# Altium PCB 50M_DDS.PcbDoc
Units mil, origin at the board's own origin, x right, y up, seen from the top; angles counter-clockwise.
Board outline 3260 x 1620 mil, 2 copper layers (Top Layer, Bottom Layer); 21 components, 21 nets, 79 pads, 0 vias.
Unrouted connection lines stored in the file: 55.
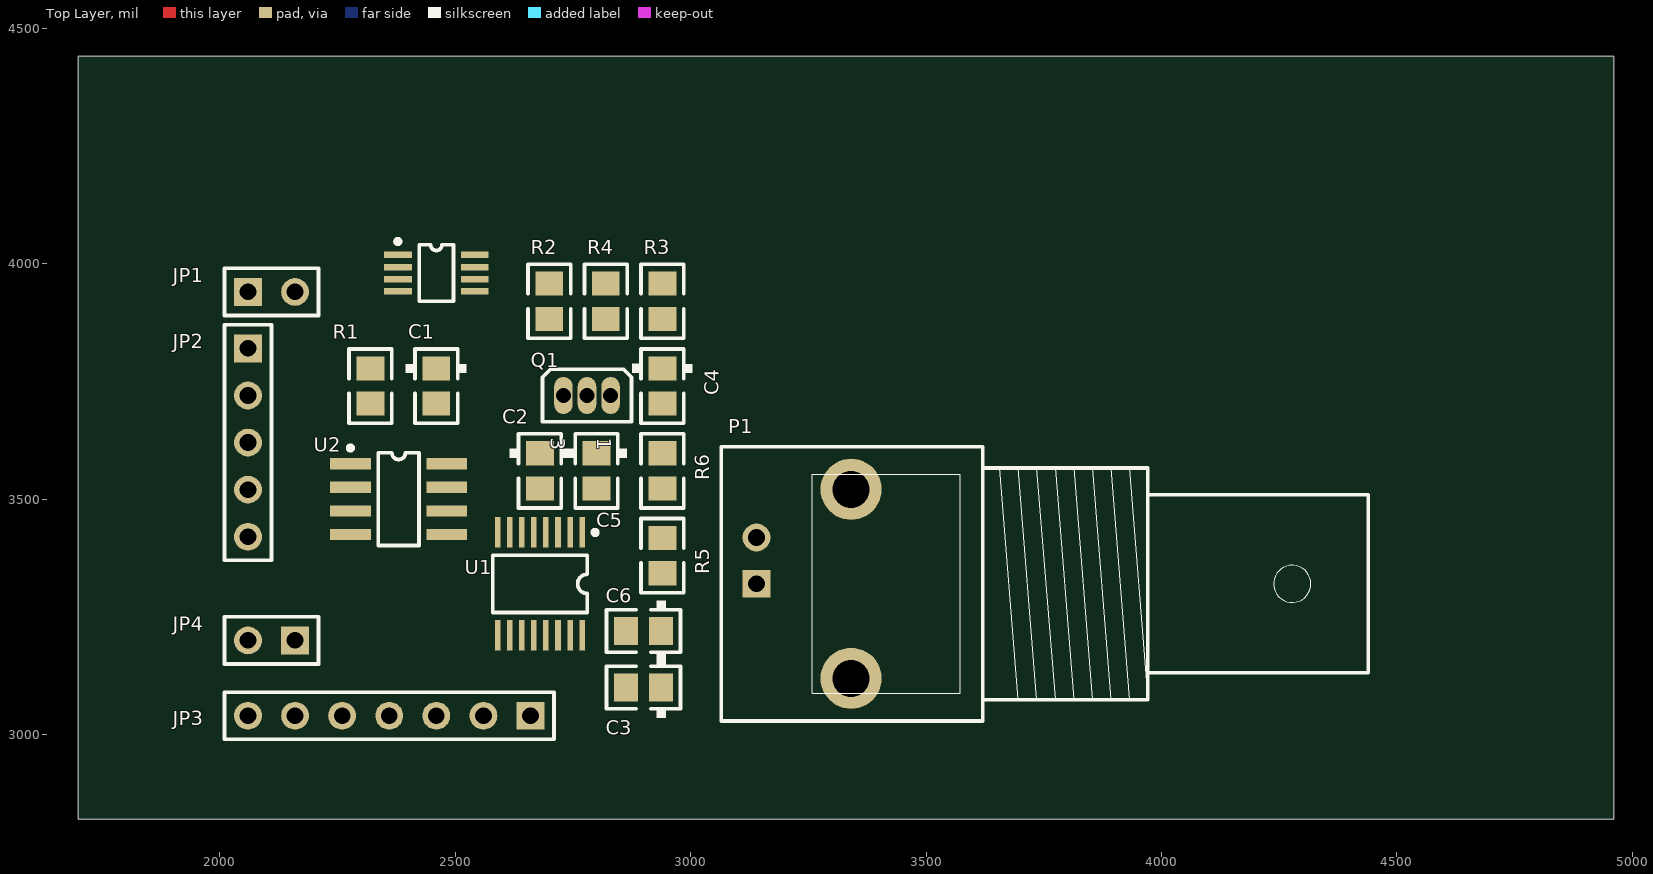
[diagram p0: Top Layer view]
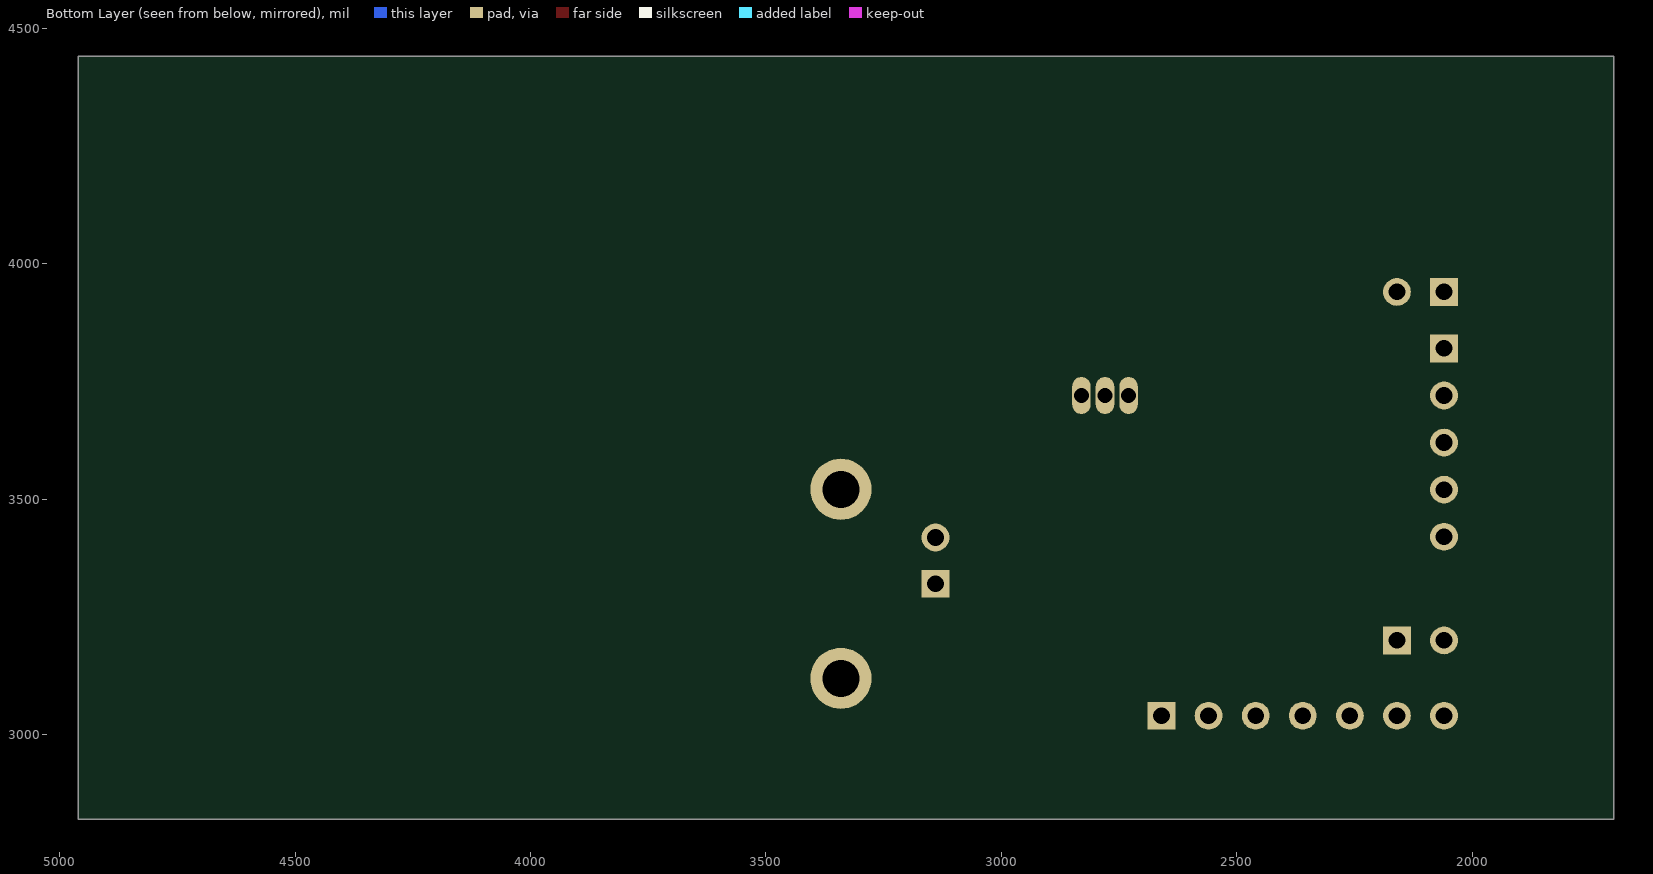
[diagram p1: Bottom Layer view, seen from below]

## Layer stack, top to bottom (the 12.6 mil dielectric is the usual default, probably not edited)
Top Layer: signal copper 1.4
Dielectric: dielectric 12.6, FR-4, Dk 4.8
Bottom Layer: signal copper 1.4

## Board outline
1700,4380 1700,2820 4960,2820 4960,4440 1700,4440

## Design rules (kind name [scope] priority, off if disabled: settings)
Clearance [All] p1: gap=10
ComponentClearance [All] p1: gap=10 collisioncheckmode=0
PolygonConnect [All] p1: connectstyle=Relief reliefconductorwidth=10 reliefentries=4 polygonreliefangle="90 Angle"
RoutingLayers [All] p1: top layer=Horizontal bottom layer=Vertical
RoutingVias [All] p1: holewidth=28 width=50 viastyle="Through Hole" minholewidth=28 minwidth=50 maxholewidth=28 maxwidth=50
SolderMaskExpansion [All] p1: expansion=4
TestPointUsage [All] p1: valid=0 allowmultiple=FALSE
Testpoint [All] p1: side=15 testpointundercomponent=TRUE minsize=40 maxsize=100 preferedsize=60 minholesize=0 maxholesize=40 preferedholesize=32 testpointgrid=1 style=1023 order=-539222988
Width [All] p1: maxlimit=10 minlimit=10 preferedwidth=10
16 further rules are at their usual default settings.

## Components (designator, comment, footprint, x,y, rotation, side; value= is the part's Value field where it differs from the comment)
C1 "100pF" CC2012-0805 2460,3740 r270 top
C2 "100pF" CC2012-0805 2680,3560 r270 top
C3 "100pF" CC2012-0805 2900,3100 r180 top
C4 "510pF" CC2012-0805 2940,3740 r270 top
C5 "100pF" CC2012-0805 2800,3560 r270 top
C6 "100pF" CC2012-0805 2900,3220 r180 top
JP1 "Header 2" HDR1X2 2060,3940 r0 top locked
JP2 "Header 5" HDR1X5 2060,3820 r270 top locked
JP3 "Header 7" HDR1X7 2660,3040 r180 top locked
JP4 "Header 2" HDR1X2 2160,3200 r180 top locked
P1 "BNC" "BNC_RA CON" 3140,3320 r180 top
Q1 "MOSFET-N" BCY-W3/H.8 2780,3720 r270 top
R1 "4.7K" R2012-0805 2320,3740 r270 top
R2 "4.7K" R2012-0805 2700,3920 r90 top
R3 "50" R2012-0805 2940,3920 r90 top
R4 "1.5K" R2012-0805 2820,3920 r270 top
R5 "300" R2012-0805 2940,3380 r270 top
R6 "4.7K" R2012-0805 2940,3560 r270 top
U1 "AD9835" TSSO5X6-G16 2680,3320 r180 top
U2 "TLC5615" SO-G8 2380,3500 r270 top
? "ADG821" TSSO3X5-G8/X.35 2460,3980 r270 top

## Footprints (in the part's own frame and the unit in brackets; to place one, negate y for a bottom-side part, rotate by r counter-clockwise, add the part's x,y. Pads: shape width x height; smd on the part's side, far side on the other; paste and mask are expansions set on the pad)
BCY-W3/H.8 [mm]
  oval 2x1 hole 0.8: 1(0,1.27) 2(0,0) 3(0,-1.27)
  silkscreen extent -1.41,-2.41 1.41,2.41
"BNC_RA CON" [mm]
  rect 1.5x1.5 hole 0.9: 1(0,0)
  round 3.3 hole 2: 2(-5.1,5.1) 2(-5.1,-5.1)
  round 1.5 hole 0.9: 2(0,-2.5)
  silkscreen extent -33,-7.4 1.9,7.4
CC2012-0805 [mm]
  rect 1.3x1.5 smd: 1(-0.95,0) 2(0.95,0)
  silkscreen extent -2,-1.65 2,1.64
HDR1X2 [mm]
  rect 1.5x1.5 hole 0.9: 1(0,0)
  round 1.5 hole 0.9: 2(2.54,0)
  silkscreen extent -1.27,-1.27 3.81,1.27
HDR1X5 [mm]
  rect 1.5x1.5 hole 0.9: 1(0,0)
  round 1.5 hole 0.9: 2(2.54,0) 3(5.08,0) 4(7.62,0) 5(10.16,0)
  silkscreen extent -1.27,-1.27 11.43,1.27
HDR1X7 [mm]
  rect 1.5x1.5 hole 0.9: 1(0,0)
  round 1.5 hole 0.9: 2(2.54,0) 3(5.08,0) 4(7.62,0) 5(10.16,0) 6(12.7,0) 7(15.24,0)
  silkscreen extent -1.27,-1.27 16.51,1.27
R2012-0805 [mm]
  rect 1.3x1.5 smd: 1(-0.95,0) 2(0.95,0)
  silkscreen extent -2,-1.15 2,1.15
SO-G8 [mm]
  rect 0.6x2.2 smd: 1(-1.905,-2.6) 2(-0.635,-2.6) 3(0.635,-2.6) 4(1.905,-2.6) 5(1.905,2.6) 6(0.635,2.6) 7(-0.635,2.6) 8(-1.905,2.6)
  silkscreen extent -2.88,-2.72 2.5,1.1
TSSO3X5-G8/X.35 [mm]
  rect 0.35x1.5 smd: 1(-0.975,-2.075) 2(-0.325,-2.075) 3(0.325,-2.075) 4(0.975,-2.075) 5(0.975,2.075) 6(0.325,2.075) 7(-0.325,2.075) 8(-0.975,2.075)
  silkscreen extent -1.82,-2.2 1.52,0.92
TSSO5X6-G16 [mm]
  rect 0.3x1.65 smd: 1(-2.275,-2.775) 2(-1.625,-2.775) 3(-0.975,-2.775) 4(-0.325,-2.775) 5(0.325,-2.775) 6(0.975,-2.775) 7(1.625,-2.775) 8(2.275,-2.775) 9(2.275,2.775) 10(1.625,2.775) 11(0.975,2.775) 12(0.325,2.775) 13(-0.325,2.775) 14(-0.975,2.775) 15(-1.625,2.775) 16(-2.275,2.775)
  silkscreen extent -3.1,-2.9 2.55,1.55

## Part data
C1 C2 C3 C4 C5 C6: library part Cap, "Capacitor"
JP1 JP4: "Header, 2-Pin"
JP2: "Header, 5-Pin"
JP3: "Header, 7-Pin"
P1: "BNC Elbow Connector"
Q1: "N-Channel MOSFET"
R1 R2 R3 R4 R5 R6: library part Res1, "Resistor"
U1: "50 MHz CMOS / Complete DDS"
U2: "10bit DA Convertor"

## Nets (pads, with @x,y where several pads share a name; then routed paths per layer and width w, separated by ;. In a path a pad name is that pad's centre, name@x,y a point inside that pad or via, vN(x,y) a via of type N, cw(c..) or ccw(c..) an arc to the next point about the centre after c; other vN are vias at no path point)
CLK: JP2.3 U2.2
D: ?.2 ?.6 Q1.2 R3.2
DIN: JP2.2 U2.1
FSEL: JP3.4 U1.10
FSYNC: JP3.5 U1.9
GND: ?.4 C1.1 C2.1 C3.1 C5.1 JP1.1 JP2.1 JP4.1 P1.1 R1.2 R3.1 R4.1 R5.1 R6.1 U1.5 U1.13 U2.3 U2.5
IN1: ?.7 JP2.5 R2.1
MCLK: JP3.1 U1.6
Net_3: ?.3 R1.1
NetC4_1: C4.1 Q1.3 R4.2
NetC5_2: C5.2 U1.2 U1.3
NetC6_2: C6.2 U1.16
NetP1_2: P1.2 R5.2 U1.14
PSEL0: JP3.2 U1.12
PSEL1: JP3.3 U1.11
RSET: C4.2 Q1.1 R6.2 U1.1
S1: ?.1 JP1.2
S2: ?.5 U2.7
SCLK: JP3.7 U1.7
SDATA: JP3.6 U1.8
VCC: ?.8 C1.2 C2.2 C3.2 C6.1 JP4.2 R2.2 U1.4 U1.15 U2.8
pads on no net: JP2.4 U2.4 U2.6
